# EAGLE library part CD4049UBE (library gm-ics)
Hex Inverting Buffer Used, for example, in the Red Llama, Three Legged Dog, and Hot Harmonics.
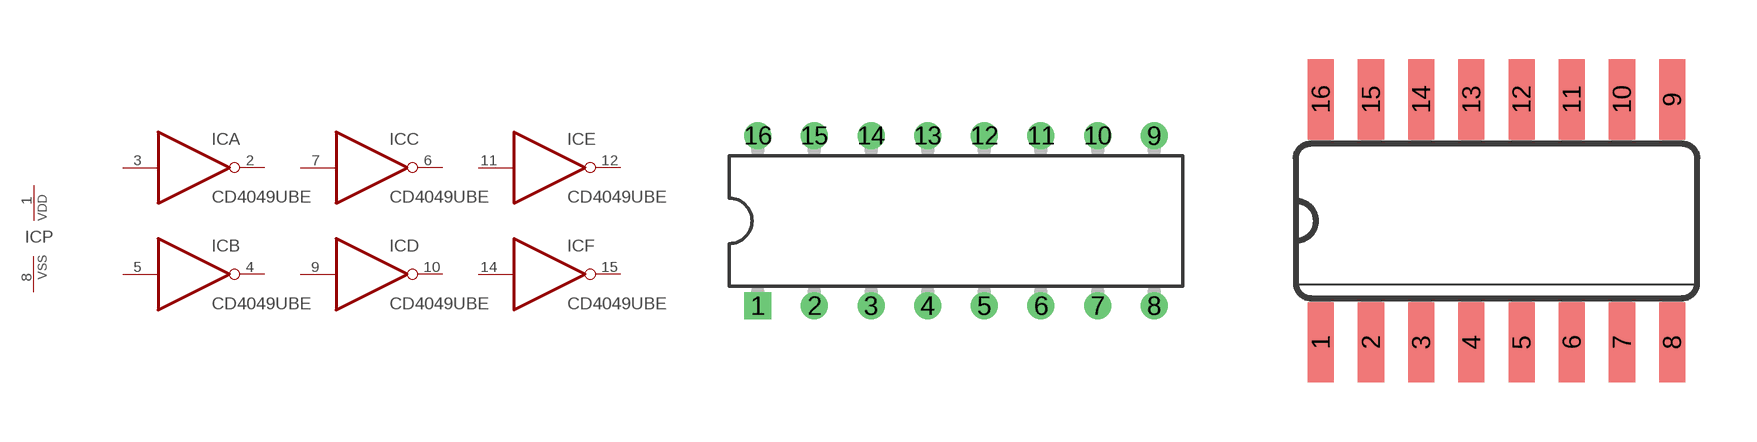
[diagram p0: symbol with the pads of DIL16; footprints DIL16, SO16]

Designator prefix IC; gates A=4049 B=4049 C=4049 D=4049 E=4049 F=4049 P=PWRN

## CD4049UBE  [DIL16]
1  P:VDD  pwr
2  A:O  out
3  A:I  in
4  B:O  out
5  B:I  in
6  C:O  out
7  C:I  in
8  P:VSS  pwr
9  D:I  in
10  D:O  out
11  E:I  in
12  E:O  out
14  F:I  in
15  F:O  out

## CD4049UBED  [SO16]
Pads as for DIL16

## Footprint DIL16 (pad centres in mm)
Dual In Line Package
drill 0.7 square: 1 -8.89,-3.81
drill 0.7 round: 2 -6.35,-3.81; 3 -3.81,-3.81; 4 -1.27,-3.81; 5 1.27,-3.81; 6 3.81,-3.81; 7 6.35,-3.81; 8 8.89,-3.81; 9 8.89,3.81; 10 6.35,3.81; 11 3.81,3.81; 12 1.27,3.81; 13 -1.27,3.81; 14 -3.81,3.81; 15 -6.35,3.81; 16 -8.89,3.81

## Footprint SO16 (pad centres in mm)
Small Outline package 150 mil
smd 0.66 x 2.032: 1 -4.445,-3.073; 2 -3.175,-3.073; 3 -1.905,-3.073; 4 -0.635,-3.073; 5 0.635,-3.073; 6 1.905,-3.073; 7 3.175,-3.073; 8 4.445,-3.073; 9 4.445,3.073; 10 3.175,3.073; 11 1.905,3.073; 12 0.635,3.073; 13 -0.635,3.073; 14 -1.905,3.073; 15 -3.175,3.073; 16 -4.445,3.073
